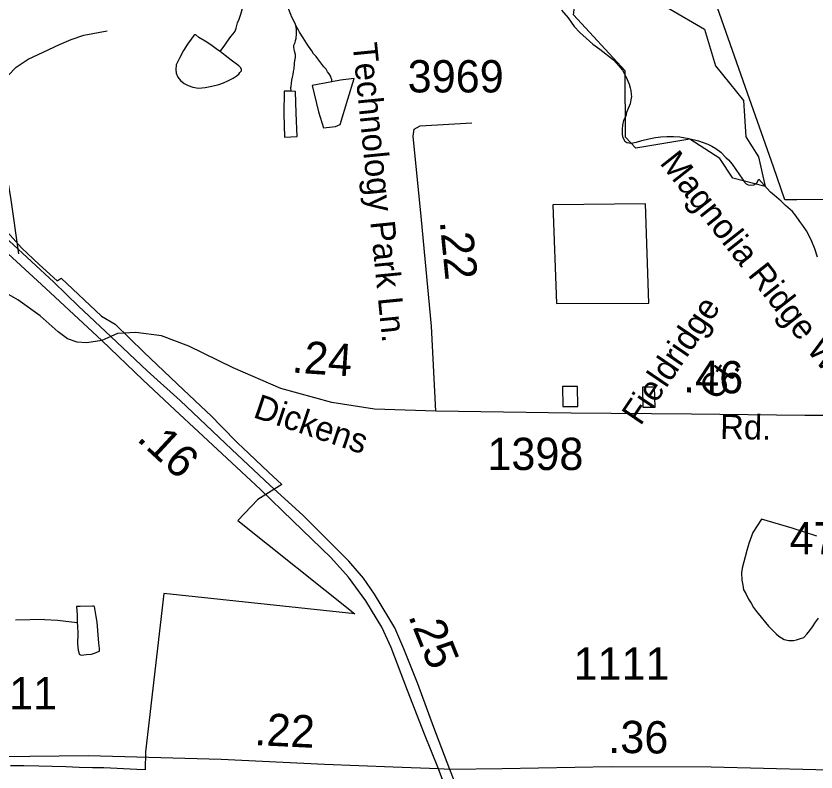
# Model space of a CAD drawing. Extents: x 2001466 to 2224147, y 644118 to 847247.
# Drawn here: x 2055654 to 2058752, y 677277 to 680203 of the extents above; entities that cross this region are included whole.
import ezdxf

# ---------------------------------------------------------------- set-up
doc = ezdxf.new("R2010")
doc.units = 0
for name, color, linetype in [('Exist Boundary Political City Limit New', 7, 'Continuous'), ('Exist Hydrographic Misc Water Feature', 7, 'Continuous'), ('Exist Road Non-System Type 51', 7, 'Continuous'), ('Exist Road Non-System Type 51 Label', 7, 'Continuous'), ('Exist Road Primary NC Divided Attributed', 7, 'Continuous'), ('Exist Road Primary NC Service Mileage Hundredths English Label', 7, 'Continuous'), ('Exist Road Secondary Mileage Hundredths English Label', 7, 'Continuous'), ('Exist Road Secondary Type 51 Attributed', 7, 'Continuous'), ('Exist Road Secondary Type 51 Label', 7, 'Continuous'), ('Exist Road Secondary Type 51 Number Label', 7, 'Continuous'), ('Map Preparation Boundary City Limit Buffer Line', 7, 'Continuous')]:
    doc.layers.add(name, color=color, linetype=linetype)

msp = doc.modelspace()

# ---------------------------------------------------------------- linework, layer by layer
at = {"layer": 'Exist Boundary Political City Limit New'}
for points in [[(2058811.8, 679493.2), (2058678, 679491.1), (2058630.8, 679491.2), (2058587, 679619.5), (2058479.4, 679926.8), (2058453.5, 680000), (2058353.2, 680284.1)], [(2055334.8, 679684.5), (2055675.1, 679305.7), (2055744.2, 679241.5), (2055813.4, 679177.4), (2055829.2, 679187.9), (2055985.2, 679041.2), (2056037.6, 679010.5), (2056148.4, 678901.4), (2056278.2, 678779.2), (2056369.2, 678693.6), (2056411.2, 678654.1), (2056447.2, 678617.4), (2056514.6, 678548.5), (2056531.6, 678532.4), (2056631.8, 678438.2), (2056682.9, 678390.1), (2056590.8, 678331.6), (2056513.5, 678250.1), (2056965.5, 677888.9), (2056226.5, 677967.8), (2056155.2, 677355.1), (2056154, 677285.6), (2056122, 677286.8), (2055994.1, 677292.7), (2055950.4, 677293.9), (2055898.4, 677295.2), (2055846.4, 677296.6), (2055794.4, 677298.1), (2055742.4, 677299.4), (2055684.4, 677301), (2055632.4, 677301.4)], [(2058104, 679091.9), (2058091.2, 679476.3), (2057732.2, 679472.6), (2057746.9, 679090.1), (2058104, 679091.9)], [(2057829.1, 678691.2), (2057827.8, 678769.1), (2057769.8, 678769.7), (2057771.4, 678691.8), (2057829.1, 678691.2)], [(2058126.6, 678766.5), (2058079.4, 678766.9), (2058081.8, 678689.2), (2058129.4, 678688.8), (2058126.6, 678766.5)]]:
    msp.add_lwpolyline(points, dxfattribs=at)
at = {"layer": 'Exist Hydrographic Misc Water Feature'}
for points in [[(2056444.4, 680065.9), (2056462.4, 680089.9), (2056470.4, 680102.1), (2056486.4, 680124), (2056494.4, 680133.8), (2056502.4, 680143.9), (2056506.5, 680155.9), (2056512, 680176.1), (2056518.2, 680190.2), (2056524.6, 680209.9), (2056530.1, 680228.1), (2056536.2, 680249.9), (2056544.2, 680279.9), (2056550, 680324.1), (2056557.8, 680363.8)], [(2056736.4, 680170.5), (2056728.4, 680186.3), (2056722.4, 680198.2), (2056718.1, 680208.6), (2056709.9, 680228.5), (2056704.2, 680244.3), (2056696, 680264.2), (2056683.9, 680286.3), (2056674, 680318.3), (2056668.1, 680332.1), (2056661.9, 680348.1), (2056649.8, 680370.2), (2056635.7, 680390.2)], [(2057828.7, 680325.4), (2057928.7, 680375.9), (2058028.6, 680351), (2058053.6, 680307.8), (2058320.6, 680151.5), (2058362.6, 680009.5), (2058470.7, 679876.1), (2058479.7, 679734.8), (2058529.6, 679658.4), (2058554.6, 679543), (2058429.7, 679575.1), (2058379.7, 679651.5), (2058263.6, 679726.1), (2058054.7, 679691), (2058013.6, 679734.5), (2058012.6, 679990.4), (2057812.7, 680207.7), (2057828.7, 680325.4)], [(2057766.3, 680226.1), (2057791.8, 680196.2), (2057816, 680162.6), (2057837.9, 680138.5), (2057862.3, 680116.6), (2057887.9, 680094.5), (2057914.4, 680074.6), (2057968.3, 680032.8), (2057988.4, 680010.7), (2058002.4, 679992.7), (2058010.2, 679978.6), (2058020.6, 679956.7), (2058028.2, 679938.9), (2058032.7, 679924.9), (2058034.4, 679914.9), (2058036.4, 679898.8), (2058036.8, 679891), (2058034.4, 679878.8), (2058032.5, 679862.8), (2058024.9, 679845), (2058018.4, 679828.9), (2058014.9, 679814.8), (2058006.5, 679798.7), (2058002.8, 679781), (2058000.9, 679764.6), (2058000.9, 679746.8), (2058002.8, 679734.7), (2058011.2, 679718.8), (2058019, 679712.8), (2058034.8, 679710.8), (2058056.7, 679714.8), (2058077, 679721.1), (2058104.7, 679727), (2058130.7, 679733.1), (2058150.6, 679735), (2058174.8, 679737), (2058200.6, 679737.1), (2058224.6, 679735.1), (2058258.9, 679729.2), (2058296.8, 679719.4), (2058332.7, 679707.4), (2058348.7, 679699.3), (2058364.5, 679689.6), (2058382.9, 679675.5), (2058402.6, 679655.4), (2058412.9, 679645.8), (2058426.8, 679629.5), (2058441, 679609.5), (2058455.1, 679587.9), (2058465, 679575.8), (2058475, 679559.7), (2058481, 679553.9), (2058489.2, 679549.8), (2058499, 679547.9), (2058511.3, 679549.7), (2058522.8, 679557.7), (2058531, 679571.9)], [(2056718.9, 679912.4), (2056718.7, 679926.2), (2056718.9, 679930.2), (2056720.6, 679942.5), (2056722.4, 679954.4), (2056724.5, 679966.7), (2056726.7, 679976.5), (2056728.6, 679988.3), (2056730.8, 679998.6), (2056732.5, 680018.6), (2056734.3, 680030.5), (2056736.8, 680042.3), (2056736.6, 680054.5), (2056732.3, 680066.5), (2056730.2, 680082.2), (2056730.2, 680090.3), (2056734.5, 680100.2), (2056736.4, 680108.4), (2056738.4, 680116.2), (2056740.3, 680134.2), (2056740.3, 680142.3), (2056740.3, 680150.4), (2056737.2, 680166.3), (2056736.4, 680170.5)], [(2056876.6, 679948.5), (2056876.8, 679956.6), (2056874.4, 679962.6), (2056872.7, 679968.5), (2056866.4, 679978.8), (2056860.4, 679986.6), (2056854.5, 679996.8), (2056846.5, 680006.6), (2056830.5, 680026.4), (2056822.5, 680036.6), (2056816.5, 680046.4), (2056806.3, 680056.5), (2056800.1, 680068.4), (2056786.2, 680086.7), (2056778.4, 680098.4), (2056772.5, 680108.2), (2056766.5, 680118.5), (2056752.4, 680140.5), (2056748.1, 680148.4), (2056737.2, 680166.3), (2056736.4, 680170.5)], [(2056444.4, 680065.9), (2056434.3, 680071.9), (2056408.3, 680091.7), (2056386.3, 680105.5), (2056362.4, 680119.7), (2056350.5, 680129.6), (2056346.4, 680129.9), (2056342.5, 680127.6), (2056332.6, 680113.7), (2056318.5, 680093.5), (2056302.7, 680069.5), (2056286.7, 680039.5), (2056274.6, 680013.4), (2056273, 679995.4), (2056274.4, 679981.8), (2056280.7, 679965.8), (2056291, 679953.7), (2056304.7, 679941.5), (2056320.7, 679933.7), (2056339, 679927.8), (2056360.7, 679923.6), (2056386.6, 679925.8), (2056412.8, 679932), (2056438.8, 679937.8), (2056456.9, 679944), (2056474.7, 679951.8), (2056494.8, 679962.1), (2056506.7, 679970.1), (2056517, 679977.9), (2056520.5, 679984.2), (2056526.6, 679990.2), (2056526.6, 679995.8), (2056524.8, 680002.2), (2056516.8, 680009.9), (2056486.8, 680031.9), (2056464.3, 680049.9), (2056444.4, 680065.9)], [(2056876.6, 679948.5), (2056800.8, 679934.4), (2056825, 679832.5), (2056844.8, 679770.7), (2056891, 679774.7), (2056909, 679782.5), (2056939, 679880.6), (2056963, 679960.9), (2056910.5, 679954.7), (2056876.6, 679948.5)], [(2056718.9, 679912.4), (2056692.9, 679912.2), (2056690.6, 679824.6), (2056693.1, 679734.5), (2056743.1, 679736.3), (2056739, 679826.6), (2056736.8, 679910.4), (2056733.1, 679910.2), (2056718.9, 679912.4)], [(2058757.6, 679270.2), (2058747.5, 679302.2), (2058735.6, 679330.4), (2058725.2, 679352.2), (2058715.3, 679371.9), (2058701.4, 679391.9), (2058689.1, 679408), (2058675.3, 679427.9), (2058661, 679445.9), (2058633.1, 679470), (2058617.1, 679485.9), (2058598.9, 679502), (2058575.1, 679521.8), (2058550.9, 679547.8), (2058531, 679571.9)], [(2058755.5, 678190.4), (2058659.4, 678220.4), (2058541.2, 678256.2), (2058507.6, 678204.1), (2058491.6, 678161.9), (2058483.4, 678133.9), (2058465.8, 678066), (2058463.7, 678048.1), (2058464.1, 678020.1), (2058468, 678000), (2058471.7, 677982), (2058480.1, 677968.2), (2058490, 677946), (2058500.2, 677930.2), (2058510.3, 677914.1), (2058522, 677898.1), (2058540, 677876.4), (2058555.8, 677856.1), (2058567.9, 677842.1), (2058583.9, 677826.3), (2058598.2, 677812.4), (2058608.5, 677802.3), (2058618.1, 677796.4), (2058628.2, 677790.4), (2058646.2, 677786.4), (2058664.5, 677786.5), (2058676.2, 677788.3), (2058688.5, 677792.6), (2058704.3, 677798.3), (2058715.9, 677810.3), (2058728.2, 677824.7), (2058738.1, 677838.6), (2058750.2, 677856.7), (2058761.7, 677872.7)], [(2055890.5, 677855.4), (2055892.6, 677841.3), (2055893, 677813.2), (2055892.6, 677773.2), (2055895, 677749.3), (2055896.7, 677739.3), (2055898.7, 677733.3), (2055906.9, 677729.2), (2055926.8, 677731.4), (2055946.7, 677733.3), (2055954.7, 677735.3), (2055976.9, 677745.4), (2055976.7, 677751.5), (2055976.9, 677755.5), (2055974.6, 677775.3), (2055968.7, 677857.3), (2055964.8, 677879.4), (2055958.4, 677917.3), (2055954.5, 677919.5), (2055950.6, 677919.3), (2055902.2, 677917.3), (2055894.6, 677917.3), (2055888.7, 677917.4), (2055890.5, 677885.4), (2055890.5, 677855.4)], [(2055764.6, 677867.2), (2055652.5, 677864.7)], [(2055764.6, 677867.2), (2055814.5, 677865.3), (2055890.5, 677855.4)]]:
    msp.add_lwpolyline(points, dxfattribs=at)
at = {"layer": 'Exist Road Non-System Type 51'}
msp.add_lwpolyline([(2055665.3, 679282.4), (2055633.7, 679501), (2055610.5, 679635.5), (2055593.2, 679769.9), (2055583, 679858.1), (2055583.7, 679892), (2055592.3, 679921.9), (2055604.8, 679947.6), (2055623.3, 679973.2), (2055654, 680004.6), (2055700.6, 680035.7), (2055759.1, 680062.5), (2055821.8, 680093.2), (2055868.2, 680112.3), (2055916.5, 680129.3), (2056006.8, 680145.5)], dxfattribs=at)
at = {"layer": 'Exist Road Primary NC Divided Attributed'}
for points in [[(2056020.8, 678962.5), (2055896.4, 679079.8), (2055799.9, 679172.3), (2055628.1, 679332.9), (2055443.7, 679506), (2055334.4, 679613.1), (2055254.7, 679699.6), (2055132.9, 679831.7), (2055072.6, 679914.9), (2054848.3, 680253.1), (2054654.8, 680559.5), (2054498.9, 680805.5), (2054272.4, 681156.2), (2054098.2, 681428.4), (2053955.9, 681676.7), (2053804.5, 681939.8), (2053686.2, 682141.3), (2053598.5, 682278), (2053523.3, 682392.8), (2053431.2, 682521.7), (2053271.8, 682729), (2053104.7, 682943.1), (2052901.5, 683195.5), (2052762.7, 683375.1)], [(2055986, 678946.8), (2055769.2, 679148.4), (2055590.5, 679312.4), (2055398.1, 679488.9), (2055292.3, 679586.9), (2055185.3, 679690.5), (2055099.9, 679787.3), (2055024.8, 679886.4), (2054808.5, 680214.4), (2054693.5, 680392.1), (2054449.9, 680770.2), (2054225.7, 681125.5), (2054053.8, 681398.8), (2053904.7, 681658.5), (2053785.2, 681868), (2053632.7, 682122), (2053545, 682262.1), (2053469.1, 682372.7), (2053370.9, 682508.1), (2053220.6, 682706.2), (2053050.6, 682923.1), (2052847.4, 683175.5), (2052731.9, 683324.9)], [(2057289.7, 677288.9), (2057235.9, 677423.6), (2057170.2, 677592.7), (2057106.2, 677759.6), (2057070.2, 677837.3), (2057008.5, 677939.1), (2056941.1, 678031.7), (2056873.7, 678107.1), (2056726.4, 678248.8), (2056600.9, 678370.1), (2056452.1, 678508.5), (2056268.5, 678678.9), (2056145, 678795.1), (2055986, 678946.8)], [(2057333.6, 677286.4), (2057272.4, 677449.9), (2057210.2, 677617.9), (2057155.3, 677753.9), (2057121.1, 677835.1), (2057097.7, 677873.9), (2057041.7, 677965.4), (2056999.4, 678027.1), (2056942.3, 678093.4), (2056766.4, 678269.4), (2056637.3, 678387.1), (2056489.9, 678525.4), (2056289.2, 678714.5), (2056161.3, 678830), (2056020.8, 678962.5)], [(2058158.8, 675105.7), (2058112.9, 675217.9), (2058086.4, 675289.6), (2058014.4, 675493.1), (2057959.6, 675641.7), (2057874.5, 675847.4), (2057790.5, 676036), (2057698, 676232.6), (2057599.5, 676480.8), (2057464.4, 676832.6), (2057334.1, 677171.6), (2057289.7, 677288.9)], [(2058183.1, 675136.2), (2058156.1, 675207.5), (2058119.5, 675317.1), (2058063.5, 675486.2), (2057993.9, 675658.8), (2057916.7, 675848.5), (2057820.2, 676060), (2057731.1, 676253.2), (2057643.4, 676478.3), (2057508.3, 676830.1), (2057381.5, 677165.3), (2057333.6, 677286.4)]]:
    msp.add_lwpolyline(points, dxfattribs=at)
at = {"layer": 'Exist Road Secondary Type 51 Attributed'}
for points in [[(2057279.8, 678673.6), (2057262.4, 679002.1), (2057223.7, 679413.8), (2057191.4, 679737.9), (2057196.1, 679764.7), (2057219, 679778.2), (2057418.6, 679789.2)], [(2055986, 678946.8), (2055928, 678937.7), (2055890.4, 678941.1), (2055854, 678953.7), (2055817.6, 678981), (2055748.1, 679042.5), (2055661.6, 679104), (2055448.8, 679225.9), (2055121.9, 679399.6), (2054897, 679528.1), (2054709.4, 679619.1), (2054587.7, 679670.4), (2054499.7, 679701.2)], [(2057279.8, 678673.6), (2057042.3, 678681.5), (2056877.4, 678707.2), (2056680.1, 678760.9), (2056495.5, 678841.4), (2056322.7, 678924.7), (2056217.8, 678965.7), (2056117.6, 678977.6), (2056047.4, 678973.6), (2056020.8, 678962.5)], [(2056020.8, 678962.5), (2055986, 678946.8)], [(2059656.9, 678641.6), (2059346.8, 678654.3), (2059015.5, 678657.4), (2058708.6, 678656.3), (2058269.9, 678661.8), (2057803.6, 678666.1), (2057279.8, 678673.6)], [(2057289.7, 677288.9), (2057114.3, 677295.4), (2056848.8, 677306), (2056448.2, 677325), (2055935.2, 677339.8), (2055707.2, 677336.6), (2055300.3, 677333.5), (2054810.5, 677348.2), (2054455.8, 677365.1), (2054180.3, 677377.8), (2054052.6, 677379.9), (2053999.8, 677365.1), (2053949.1, 677327.1), (2053911.1, 677280.6), (2053890.5, 677223.6), (2053806.1, 676839.1), (2053720.6, 676471.5), (2053642.5, 676112.4), (2053595.5, 675934.9)], [(2059220, 677278.1), (2059075.4, 677279.4), (2058751.2, 677285.3), (2058346.4, 677295.9), (2057959, 677297.1), (2057536.3, 677289.9), (2057333.6, 677286.4)], [(2057333.6, 677286.4), (2057289.7, 677288.9)]]:
    msp.add_lwpolyline(points, dxfattribs=at)
at = {"layer": 'Map Preparation Boundary City Limit Buffer Line'}
for points in [[(2058811.8, 679493.2), (2058678, 679491.1), (2058630.8, 679491.2), (2058587, 679619.5), (2058479.4, 679926.8), (2058453.5, 680000), (2058353.2, 680284.1)], [(2055334.8, 679684.5), (2055675.1, 679305.7), (2055744.2, 679241.5), (2055813.4, 679177.4), (2055829.2, 679187.9), (2055985.2, 679041.2), (2056037.6, 679010.5), (2056148.4, 678901.4), (2056278.2, 678779.2), (2056369.2, 678693.6), (2056411.2, 678654.1), (2056447.2, 678617.4), (2056514.6, 678548.5), (2056531.6, 678532.4), (2056631.8, 678438.2), (2056682.9, 678390.1), (2056590.8, 678331.6), (2056513.5, 678250.1), (2056965.5, 677888.9), (2056226.5, 677967.8), (2056155.2, 677355.1), (2056154, 677285.6), (2056122, 677286.8), (2055994.1, 677292.7), (2055950.4, 677293.9), (2055898.4, 677295.2), (2055846.4, 677296.6), (2055794.4, 677298.1), (2055742.4, 677299.4), (2055684.4, 677301), (2055632.4, 677301.4)], [(2058104, 679091.9), (2058091.2, 679476.3), (2057732.2, 679472.6), (2057746.9, 679090.1), (2058104, 679091.9)], [(2057829.1, 678691.2), (2057827.8, 678769.1), (2057769.8, 678769.7), (2057771.4, 678691.8), (2057829.1, 678691.2)], [(2058126.6, 678766.5), (2058079.4, 678766.9), (2058081.8, 678689.2), (2058129.4, 678688.8), (2058126.6, 678766.5)]]:
    msp.add_lwpolyline(points, dxfattribs=at)

# ---------------------------------------------------------------- texts
at = {"layer": 'Exist Road Non-System Type 51 Label'}
for s, rotation, p in [('Magnolia Ridge Way', 308.2428, (2058143.8, 679633.4)), ('Fieldridge', 55.8741, (2058072.1, 678614)), ('Ct.', 55.8741, (2058371.1, 678710.3))]:
    msp.add_text(s, height=95, rotation=rotation, dxfattribs=at).set_placement(p)
at = {"layer": 'Exist Road Primary NC Service Mileage Hundredths English Label'}
for s, rotation, p in [('.16', 317.1275, (2056117.8, 678563)), ('.25', 291.9567, (2057171.5, 677881))]:
    msp.add_text(s, height=125, rotation=rotation, dxfattribs=at).set_placement(p)
at = {"layer": 'Exist Road Secondary Mileage Hundredths English Label'}
for s, rotation, p in [('.22', 275.6955, (2057294.5, 679408.3)), ('.24', 356.1113, (2056720, 678823.5)), ('.46', 358.8366, (2058236.6, 678746.4)), ('.22', 357.2825, (2056575.8, 677381.5)), ('.36', 359.2652, (2057947, 677351.4))]:
    msp.add_text(s, height=125, rotation=rotation, dxfattribs=at).set_placement(p)
at = {"layer": 'Exist Road Secondary Type 51 Label'}
for s, rotation, p in [('Technology Park Ln.', 275.6955, (2056957.1, 680095.5)), ('Dickens', 341.3099, (2056568.4, 678651.2)), ('Rd.', 358.8366, (2058379.9, 678566.7))]:
    msp.add_text(s, height=95, rotation=rotation, dxfattribs=at).set_placement(p)
at = {"layer": 'Exist Road Secondary Type 51 Number Label'}
for s, p in [('3969', (2057170.7, 679907.1)), ('1398', (2057479.3, 678445.8)), ('4757', (2058649.5, 678119.2)), ('1111', (2057813.1, 677634.3)), ('1111', (2055441.1, 677519.4))]:
    msp.add_text(s, height=125, dxfattribs=at).set_placement(p)

doc.saveas('drawing.dxf')
